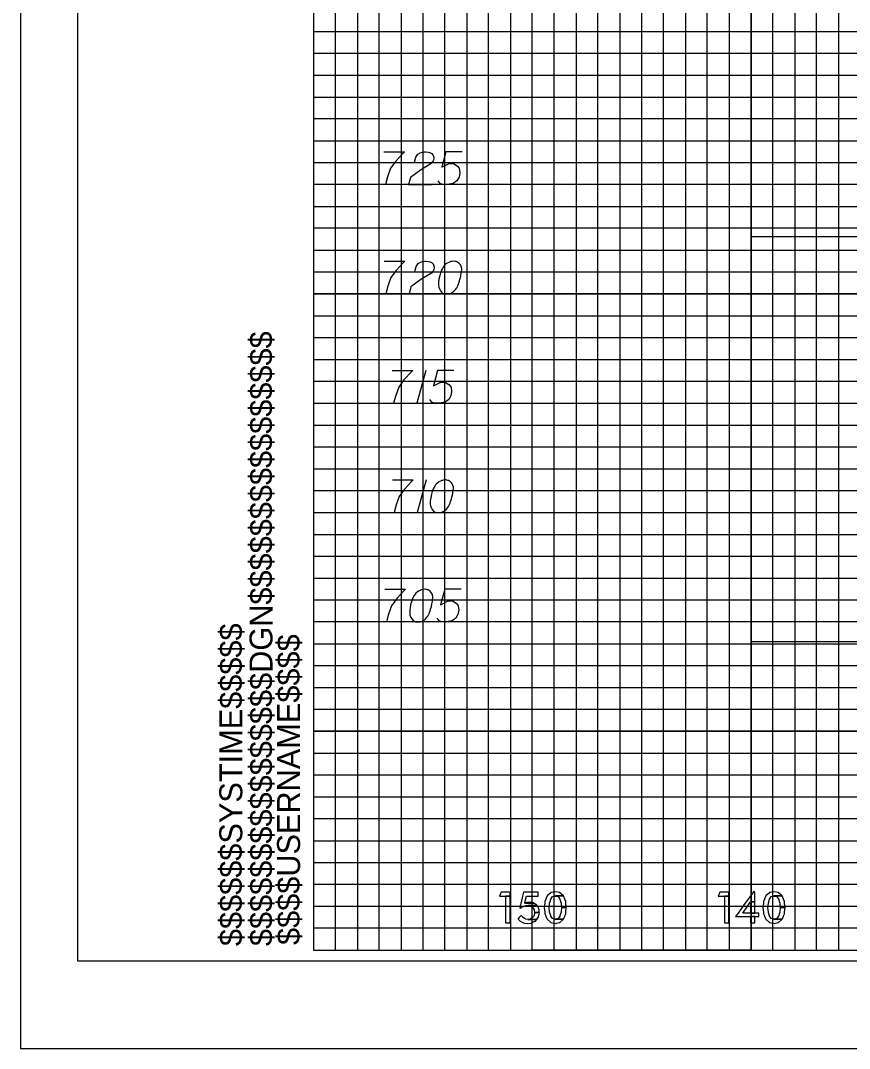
# Model space of a CAD drawing. Extents: x -13 to 323, y -5 to 1431.
# Drawn here: x -13.4 to 24.5, y 1095.5 to 1142.5 of the extents above; entities that cross this region are included whole.
import ezdxf

# ---------------------------------------------------------------- set-up
doc = ezdxf.new("R2010")
doc.units = 0
for name, color, linetype in [('Prop XS Elevation Labels', 7, 'Continuous'), ('Prop XS Offset Labels', 7, 'Continuous'), ('Scratch_Level_3', 7, 'Continuous'), ('Sheet Cross Section CELL', 7, 'Continuous'), ('Sheet Cross Section Grid Major CELL', 7, 'Continuous'), ('Sheet Cross Section Grid Middle CELL', 7, 'Continuous'), ('Sheet Cross Section Grid Minor 1 CELL', 7, 'Continuous'), ('Sheet Cross Section Grid Minor 2 CELL', 7, 'Continuous'), ('Sheet Cutting Line CELL', 7, 'Continuous'), ('Sheet DOT Grid CELL', 7, 'Continuous'), ('Sheet Plot Border Inside CELL', 7, 'Continuous'), ('Sheet Plot Border Outside CELL', 7, 'Continuous')]:
    doc.layers.add(name, color=color, linetype=linetype)

msp = doc.modelspace()

# ---------------------------------------------------------------- linework, layer by layer
at = {"layer": 'Prop XS Elevation Labels'}
for p, q in [((5.124, 1126.5), (4.723, 1125)), ((5.142, 1121.5), (4.74, 1120))]:
    msp.add_line(p, q, dxfattribs=at)
for points in [[(3.211, 1136.5), (4.155, 1136.5), (4.096, 1136.441), (3.754, 1136.075), (3.518, 1135.744), (3.376, 1135.354), (3.281, 1135)], [(4.616, 1136.028), (4.675, 1136.252), (4.77, 1136.394), (4.876, 1136.453), (4.982, 1136.488), (5.065, 1136.5), (5.124, 1136.5), (5.23, 1136.488), (5.301, 1136.465), (5.337, 1136.453), (5.408, 1136.417), (5.443, 1136.37), (5.467, 1136.323), (5.478, 1136.287), (5.49, 1136.24), (5.49, 1136.181), (5.478, 1136.122), (5.467, 1136.087), (5.443, 1136.039), (5.408, 1135.992), (5.372, 1135.957), (4.888, 1135.661), (4.427, 1135.319), (4.345, 1135), (5.419, 1135)], [(6.789, 1136.5), (6.045, 1136.5), (5.856, 1135.791), (6.199, 1135.969), (6.4, 1135.969), (6.565, 1135.862), (6.66, 1135.744), (6.683, 1135.543), (6.648, 1135.342), (6.553, 1135.177), (6.388, 1135.047), (6.104, 1135), (5.892, 1135), (5.785, 1135.047), (5.691, 1135.177)], [(3.228, 1131.5), (4.173, 1131.5), (4.114, 1131.441), (3.772, 1131.075), (3.535, 1130.744), (3.394, 1130.354), (3.299, 1130)], [(4.634, 1131.028), (4.693, 1131.252), (4.787, 1131.394), (4.894, 1131.453), (5, 1131.488), (5.083, 1131.5), (5.142, 1131.5), (5.248, 1131.488), (5.319, 1131.465), (5.354, 1131.453), (5.425, 1131.417), (5.461, 1131.37), (5.484, 1131.323), (5.496, 1131.287), (5.508, 1131.24), (5.508, 1131.181), (5.496, 1131.122), (5.484, 1131.087), (5.461, 1131.039), (5.425, 1130.992), (5.39, 1130.957), (4.906, 1130.661), (4.445, 1130.319), (4.362, 1130), (5.437, 1130)], [(6.417, 1131.5), (6.394, 1131.5), (6.323, 1131.488), (6.276, 1131.476), (6.24, 1131.465), (6.181, 1131.441), (6.11, 1131.406), (6.051, 1131.37), (5.992, 1131.323), (5.957, 1131.276), (5.921, 1131.217), (5.886, 1131.158), (5.85, 1131.087), (5.827, 1131.039), (5.803, 1130.969), (5.768, 1130.85), (5.732, 1130.673), (5.709, 1130.531), (5.709, 1130.402), (5.721, 1130.307), (5.768, 1130.201), (5.803, 1130.142), (5.862, 1130.071), (5.933, 1130.024), (5.968, 1130.012), (6.039, 1130), (6.098, 1130), (6.193, 1130.012), (6.276, 1130.035), (6.335, 1130.071), (6.417, 1130.13), (6.453, 1130.165), (6.5, 1130.213), (6.535, 1130.26), (6.559, 1130.295), (6.583, 1130.354), (6.594, 1130.378), (6.618, 1130.437), (6.642, 1130.508), (6.665, 1130.579), (6.677, 1130.626), (6.689, 1130.661), (6.701, 1130.709), (6.724, 1130.815), (6.736, 1130.874), (6.748, 1130.933), (6.76, 1131.016), (6.772, 1131.122), (6.772, 1131.158), (6.76, 1131.205), (6.748, 1131.252), (6.713, 1131.323), (6.677, 1131.37), (6.642, 1131.406), (6.594, 1131.441), (6.547, 1131.465), (6.512, 1131.476), (6.476, 1131.488), (6.417, 1131.5)], [(3.589, 1126.5), (4.533, 1126.5), (4.474, 1126.441), (4.132, 1126.075), (3.896, 1125.744), (3.754, 1125.354), (3.659, 1125)], [(6.411, 1126.5), (5.667, 1126.5), (5.478, 1125.791), (5.821, 1125.969), (6.022, 1125.969), (6.187, 1125.862), (6.282, 1125.744), (6.305, 1125.543), (6.27, 1125.342), (6.175, 1125.177), (6.01, 1125.047), (5.726, 1125), (5.514, 1125), (5.408, 1125.047), (5.313, 1125.177)], [(3.606, 1121.5), (4.551, 1121.5), (4.492, 1121.441), (4.149, 1121.075), (3.913, 1120.744), (3.772, 1120.354), (3.677, 1120)], [(6.039, 1121.5), (6.016, 1121.5), (5.945, 1121.488), (5.898, 1121.476), (5.862, 1121.465), (5.803, 1121.441), (5.732, 1121.406), (5.673, 1121.37), (5.614, 1121.323), (5.579, 1121.276), (5.543, 1121.217), (5.508, 1121.158), (5.472, 1121.087), (5.449, 1121.039), (5.425, 1120.969), (5.39, 1120.85), (5.354, 1120.673), (5.331, 1120.531), (5.331, 1120.402), (5.343, 1120.307), (5.39, 1120.201), (5.425, 1120.142), (5.484, 1120.071), (5.555, 1120.024), (5.591, 1120.012), (5.661, 1120), (5.72, 1120), (5.815, 1120.012), (5.898, 1120.035), (5.957, 1120.071), (6.039, 1120.13), (6.075, 1120.165), (6.122, 1120.213), (6.157, 1120.26), (6.181, 1120.295), (6.205, 1120.354), (6.217, 1120.378), (6.24, 1120.437), (6.264, 1120.508), (6.287, 1120.579), (6.299, 1120.626), (6.311, 1120.661), (6.323, 1120.709), (6.347, 1120.815), (6.358, 1120.874), (6.37, 1120.933), (6.382, 1121.016), (6.394, 1121.122), (6.394, 1121.158), (6.382, 1121.205), (6.37, 1121.252), (6.335, 1121.323), (6.299, 1121.37), (6.264, 1121.406), (6.217, 1121.441), (6.169, 1121.465), (6.134, 1121.476), (6.098, 1121.488), (6.039, 1121.5)], [(3.258, 1116.5), (4.203, 1116.5), (4.144, 1116.441), (3.801, 1116.075), (3.565, 1115.744), (3.423, 1115.354), (3.329, 1115)], [(5.1, 1116.5), (5.077, 1116.5), (5.006, 1116.488), (4.959, 1116.476), (4.923, 1116.465), (4.864, 1116.441), (4.793, 1116.406), (4.734, 1116.37), (4.675, 1116.323), (4.64, 1116.276), (4.604, 1116.217), (4.569, 1116.158), (4.534, 1116.087), (4.51, 1116.039), (4.486, 1115.969), (4.451, 1115.85), (4.415, 1115.673), (4.392, 1115.531), (4.392, 1115.402), (4.404, 1115.307), (4.451, 1115.201), (4.486, 1115.142), (4.545, 1115.071), (4.616, 1115.024), (4.652, 1115.012), (4.723, 1115), (4.781, 1115), (4.876, 1115.012), (4.959, 1115.035), (5.018, 1115.071), (5.1, 1115.13), (5.136, 1115.165), (5.183, 1115.213), (5.219, 1115.26), (5.242, 1115.295), (5.266, 1115.354), (5.278, 1115.378), (5.301, 1115.437), (5.325, 1115.508), (5.349, 1115.579), (5.36, 1115.626), (5.372, 1115.661), (5.384, 1115.709), (5.408, 1115.815), (5.419, 1115.874), (5.431, 1115.933), (5.443, 1116.016), (5.455, 1116.122), (5.455, 1116.158), (5.443, 1116.205), (5.431, 1116.252), (5.396, 1116.323), (5.36, 1116.37), (5.325, 1116.406), (5.278, 1116.441), (5.23, 1116.465), (5.195, 1116.476), (5.16, 1116.488), (5.1, 1116.5)], [(6.742, 1116.5), (5.998, 1116.5), (5.809, 1115.791), (6.152, 1115.969), (6.352, 1115.969), (6.518, 1115.862), (6.612, 1115.744), (6.636, 1115.543), (6.6, 1115.342), (6.506, 1115.177), (6.341, 1115.047), (6.057, 1115), (5.845, 1115), (5.738, 1115.047), (5.644, 1115.177)]]:
    msp.add_lwpolyline(points, dxfattribs=at)
at = {"layer": 'Prop XS Offset Labels'}
for points in [[(8.581, 1102.641), (8.492, 1102.459), (8.99, 1102.459), (8.99, 1102.641)], [(9.427, 1101.94), (9.424, 1101.928), (9.495, 1101.928), (9.508, 1101.94), (9.524, 1101.954), (9.595, 1101.997), (9.627, 1102.007), (9.697, 1102.029), (9.811, 1102.035), (10.219, 1102.035), (10.211, 1102.05), (10.076, 1102.145), (9.655, 1102.145), (9.658, 1102.158), (9.658, 1102.158), (9.663, 1102.178), (9.738, 1102.456), (10.263, 1102.456), (10.263, 1102.641), (9.6, 1102.641), (9.554, 1102.456), (9.486, 1102.178), (9.481, 1102.158), (9.478, 1102.145), (9.454, 1102.05), (9.451, 1102.035), (9.449, 1102.029), (9.444, 1102.007), (9.441, 1101.997), (9.431, 1101.954)], [(10.851, 1101.255), (11.051, 1101.214), (11.245, 1101.255), (11.256, 1101.257), (11.422, 1101.409), (11.047, 1101.409), (11.038, 1101.411), (11.033, 1101.413), (10.928, 1101.442), (10.841, 1101.555), (10.841, 1101.556), (10.841, 1101.556), (10.813, 1101.657), (10.813, 1101.659), (10.793, 1101.732), (10.792, 1101.736), (10.774, 1101.939), (10.774, 1101.941), (10.774, 1101.943), (10.792, 1102.145), (10.812, 1102.222), (10.813, 1102.224), (10.839, 1102.322), (10.84, 1102.325), (10.928, 1102.44), (11.041, 1102.469), (11.045, 1102.47), (11.055, 1102.473), (11.425, 1102.473), (11.262, 1102.622), (11.254, 1102.624), (11.053, 1102.668), (11.053, 1102.668), (10.845, 1102.624), (10.843, 1102.622), (10.681, 1102.473), (10.678, 1102.47), (10.678, 1102.469), (10.665, 1102.44), (10.618, 1102.325), (10.617, 1102.322), (10.577, 1102.224), (10.576, 1102.222), (10.568, 1102.145), (10.547, 1101.943), (10.547, 1101.941), (10.547, 1101.939), (10.567, 1101.736), (10.568, 1101.732), (10.575, 1101.659), (10.575, 1101.657), (10.616, 1101.556), (10.617, 1101.555), (10.663, 1101.442), (10.675, 1101.413), (10.676, 1101.411), (10.679, 1101.409), (10.848, 1101.257)], [(18.581, 1102.641), (18.492, 1102.459), (18.99, 1102.459), (18.99, 1102.641)], [(19.411, 1101.693), (19.297, 1101.534), (20.35, 1101.534), (20.35, 1101.693), (19.618, 1101.693), (19.878, 1102.059), (19.935, 1102.139), (19.977, 1102.199), (20.179, 1102.199), (20.179, 1102.668), (20.114, 1102.668), (19.775, 1102.199), (19.733, 1102.139), (19.675, 1102.059)], [(20.851, 1101.255), (21.051, 1101.214), (21.245, 1101.255), (21.256, 1101.257), (21.422, 1101.409), (21.047, 1101.409), (21.038, 1101.411), (21.033, 1101.413), (20.928, 1101.442), (20.841, 1101.555), (20.841, 1101.556), (20.841, 1101.556), (20.813, 1101.657), (20.813, 1101.659), (20.793, 1101.732), (20.792, 1101.736), (20.774, 1101.939), (20.774, 1101.941), (20.774, 1101.943), (20.792, 1102.145), (20.812, 1102.222), (20.813, 1102.224), (20.839, 1102.322), (20.84, 1102.325), (20.928, 1102.44), (21.041, 1102.469), (21.045, 1102.47), (21.055, 1102.473), (21.425, 1102.473), (21.262, 1102.622), (21.254, 1102.624), (21.053, 1102.668), (21.053, 1102.668), (20.845, 1102.624), (20.843, 1102.622), (20.681, 1102.473), (20.678, 1102.47), (20.678, 1102.469), (20.665, 1102.44), (20.618, 1102.325), (20.617, 1102.322), (20.577, 1102.224), (20.576, 1102.222), (20.568, 1102.145), (20.547, 1101.943), (20.547, 1101.941), (20.547, 1101.939), (20.567, 1101.736), (20.567, 1101.732), (20.575, 1101.659), (20.575, 1101.657), (20.616, 1101.556), (20.617, 1101.555), (20.663, 1101.442), (20.675, 1101.413), (20.676, 1101.411), (20.679, 1101.409), (20.848, 1101.257)], [(8.781, 1102.459), (8.781, 1101.25), (8.99, 1101.25), (8.99, 1102.459)], [(9.692, 1102.158), (9.655, 1102.145), (10.076, 1102.145), (10.058, 1102.158), (9.961, 1102.178), (9.75, 1102.178)], [(9.888, 1102.192), (9.75, 1102.178), (9.96, 1102.178), (9.888, 1102.192)], [(11.312, 1102.145), (11.328, 1101.943), (11.555, 1101.943), (11.536, 1102.145), (11.528, 1102.222), (11.527, 1102.224), (11.527, 1102.224), (11.488, 1102.322), (11.488, 1102.322), (11.487, 1102.325), (11.441, 1102.44), (11.44, 1102.44), (11.429, 1102.469), (11.428, 1102.47), (11.425, 1102.473), (11.055, 1102.473), (11.065, 1102.47), (11.068, 1102.469), (11.175, 1102.44), (11.262, 1102.325), (11.265, 1102.322), (11.291, 1102.224), (11.291, 1102.222)], [(18.781, 1102.459), (18.781, 1101.25), (18.99, 1101.25), (18.99, 1102.459)], [(19.97, 1102.059), (19.97, 1101.693), (20.179, 1101.693), (20.179, 1102.059), (20.179, 1102.139), (20.179, 1102.199), (19.977, 1102.199), (19.973, 1102.139)], [(21.312, 1102.145), (21.328, 1101.943), (21.555, 1101.943), (21.536, 1102.145), (21.528, 1102.222), (21.527, 1102.224), (21.527, 1102.224), (21.488, 1102.322), (21.488, 1102.322), (21.487, 1102.325), (21.441, 1102.44), (21.44, 1102.44), (21.429, 1102.469), (21.428, 1102.47), (21.425, 1102.473), (21.055, 1102.473), (21.065, 1102.47), (21.068, 1102.469), (21.175, 1102.44), (21.262, 1102.325), (21.265, 1102.322), (21.291, 1102.224), (21.291, 1102.222)], [(9.424, 1101.928), (9.482, 1101.916), (9.495, 1101.928)], [(9.9, 1101.418), (9.793, 1101.399), (10.204, 1101.399), (10.22, 1101.418), (10.221, 1101.419), (10.222, 1101.42), (10.222, 1101.42), (10.259, 1101.466), (10.268, 1101.477), (10.27, 1101.483), (10.284, 1101.535), (10.299, 1101.59), (10.322, 1101.674), (10.318, 1101.721), (10.105, 1101.721), (10.097, 1101.674), (10.082, 1101.59), (10.047, 1101.535), (10.014, 1101.483), (10.004, 1101.477), (9.987, 1101.466), (9.913, 1101.42), (9.905, 1101.419)], [(10.083, 1101.841), (10.105, 1101.721), (10.318, 1101.721), (10.307, 1101.841), (10.307, 1101.841), (10.303, 1101.881), (10.284, 1101.916), (10.278, 1101.928), (10.271, 1101.94), (10.263, 1101.954), (10.24, 1101.997), (10.235, 1102.007), (10.223, 1102.029), (10.219, 1102.035), (9.811, 1102.035), (9.838, 1102.029), (9.928, 1102.007), (9.943, 1101.997), (10.003, 1101.954), (10.024, 1101.94), (10.031, 1101.928), (10.038, 1101.916), (10.059, 1101.881)], [(11.058, 1101.411), (11.047, 1101.409), (11.422, 1101.409), (11.425, 1101.411), (11.426, 1101.413), (11.438, 1101.442), (11.485, 1101.555), (11.485, 1101.556), (11.527, 1101.657), (11.528, 1101.659), (11.535, 1101.732), (11.535, 1101.736), (11.555, 1101.939), (11.556, 1101.941), (11.555, 1101.943), (11.328, 1101.943), (11.328, 1101.941), (11.328, 1101.939), (11.312, 1101.736), (11.312, 1101.732), (11.292, 1101.659), (11.291, 1101.657), (11.264, 1101.556), (11.263, 1101.555), (11.175, 1101.442), (11.063, 1101.413)], [(21.058, 1101.411), (21.047, 1101.409), (21.422, 1101.409), (21.425, 1101.411), (21.426, 1101.413), (21.438, 1101.442), (21.485, 1101.555), (21.485, 1101.556), (21.527, 1101.657), (21.528, 1101.659), (21.535, 1101.732), (21.535, 1101.736), (21.555, 1101.939), (21.556, 1101.941), (21.555, 1101.943), (21.328, 1101.943), (21.328, 1101.941), (21.328, 1101.939), (21.312, 1101.736), (21.312, 1101.732), (21.292, 1101.659), (21.291, 1101.657), (21.264, 1101.556), (21.263, 1101.555), (21.175, 1101.442), (21.063, 1101.413)], [(9.626, 1101.233), (9.762, 1101.214), (9.959, 1101.233), (9.968, 1101.237), (10.091, 1101.297), (10.091, 1101.297), (10.141, 1101.321), (10.185, 1101.375), (10.204, 1101.399), (9.793, 1101.399), (9.683, 1101.418), (9.682, 1101.419), (9.679, 1101.42), (9.596, 1101.466), (9.586, 1101.477), (9.58, 1101.483), (9.58, 1101.483), (9.529, 1101.535), (9.497, 1101.585), (9.497, 1101.585), (9.451, 1101.535), (9.404, 1101.483), (9.399, 1101.477), (9.39, 1101.466), (9.348, 1101.42), (9.347, 1101.419), (9.348, 1101.418), (9.363, 1101.399), (9.382, 1101.375), (9.445, 1101.321), (9.474, 1101.297), (9.598, 1101.237)], [(19.97, 1101.534), (19.97, 1101.25), (20.179, 1101.25), (20.179, 1101.534)]]:
    msp.add_lwpolyline(points, close=True, dxfattribs=at)
at = {"layer": 'Scratch_Level_3'}
msp.add_lwpolyline([(20, 1132.62), (300, 1132.62), (300, 1114.089), (20, 1114.089)], close=True, dxfattribs=at)
at = {"layer": 'Sheet Cross Section CELL'}
msp.add_line((0, 1100), (0, 1100), dxfattribs=at)
msp.add_line((0, 1100), (0, 1100), dxfattribs=at)
msp.add_line((0, 1100), (0, 1100), dxfattribs=at)
msp.add_line((0, 1100), (0, 1100), dxfattribs=at)
msp.add_line((0, 1100), (0, 1100), dxfattribs=at)
msp.add_line((0, 1100), (0, 1100), dxfattribs=at)
msp.add_line((0, 1100), (0, 1100), dxfattribs=at)
msp.add_lwpolyline([(320, 1310), (0, 1310), (0, 1100), (320, 1100)], close=True, dxfattribs=at)
at = {"layer": 'Sheet Cross Section Grid Major CELL'}
for p, q in [((10, 1100), (10, 1310)), ((20, 1310), (20, 1100)), ((20, 1100), (10, 1100))]:
    msp.add_line(p, q, dxfattribs=at)
for points in [[(0, 1140), (320, 1140), (320, 1130), (0, 1130)], [(0, 1120), (320, 1120), (320, 1110), (0, 1110)]]:
    msp.add_lwpolyline(points, dxfattribs=at)
at = {"layer": 'Sheet Cross Section Grid Middle CELL'}
for points in [[(5, 1310), (5, 1100), (15, 1100), (15, 1310)], [(0, 1125), (320, 1125), (320, 1135), (0, 1135)], [(0, 1105), (320, 1105), (320, 1115), (0, 1115)]]:
    msp.add_lwpolyline(points, dxfattribs=at)
at = {"layer": 'Sheet Cross Section Grid Minor 1 CELL'}
for points in [[(0, 1142), (320, 1142), (320, 1141), (0, 1141)], [(0, 1139), (320, 1139), (320, 1138), (0, 1138)], [(0, 1137), (320, 1137), (320, 1136), (0, 1136)], [(0, 1134), (320, 1134), (320, 1133), (0, 1133)], [(0, 1132), (320, 1132), (320, 1131), (0, 1131)], [(0, 1129), (320, 1129), (320, 1128), (0, 1128)], [(0, 1127), (320, 1127), (320, 1126), (0, 1126)], [(0, 1124), (320, 1124), (320, 1123), (0, 1123)], [(0, 1122), (320, 1122), (320, 1121), (0, 1121)], [(0, 1119), (320, 1119), (320, 1118), (0, 1118)], [(0, 1117), (320, 1117), (320, 1116), (0, 1116)], [(0, 1114), (320, 1114), (320, 1113), (0, 1113)], [(0, 1112), (320, 1112), (320, 1111), (0, 1111)], [(0, 1109), (320, 1109), (320, 1108), (0, 1108)], [(0, 1107), (320, 1107), (320, 1106), (0, 1106)], [(0, 1104), (320, 1104), (320, 1103), (0, 1103)], [(0, 1102), (320, 1102), (320, 1101), (0, 1101)]]:
    msp.add_lwpolyline(points, dxfattribs=at)
at = {"layer": 'Sheet Cross Section Grid Minor 2 CELL'}
for points in [[(0, 1100), (1, 1100), (1, 1310), (2, 1310), (2, 1100)], [(2, 1100), (3, 1100), (3, 1310), (4, 1310), (4, 1100)], [(5, 1100), (6, 1100), (6, 1310), (7, 1310), (7, 1100)], [(7, 1100), (8, 1100), (8, 1310), (9, 1310), (9, 1100)], [(10, 1100), (11, 1100), (11, 1310), (12, 1310), (12, 1100)], [(12, 1100), (13, 1100), (13, 1310), (14, 1310), (14, 1100)], [(15, 1100), (16, 1100), (16, 1310), (17, 1310), (17, 1100)], [(17, 1100), (18, 1100), (18, 1310), (19, 1310), (19, 1100)], [(20, 1100), (21, 1100), (21, 1310), (22, 1310), (22, 1100)], [(22, 1100), (23, 1100), (23, 1310), (24, 1310), (24, 1100)]]:
    msp.add_lwpolyline(points, dxfattribs=at)
at = {"layer": 'Sheet Cutting Line CELL'}
for p, q in [((-13.4, 1314.5), (-13.4, 1095.5)), ((-13.4, 1095.5), (323.3, 1095.5))]:
    msp.add_line(p, q, dxfattribs=at)
at = {"layer": 'Sheet DOT Grid CELL'}
for p, q in [((10, 1100), (10, 1310)), ((20, 1100), (20, 1310)), ((0, 1140), (320, 1140)), ((0, 1130), (320, 1130)), ((0, 1120), (320, 1120)), ((0, 1110), (320, 1110))]:
    msp.add_line(p, q, dxfattribs=at)
at = {"layer": 'Sheet Plot Border Inside CELL'}
msp.add_lwpolyline([(-10.8, 1099.5), (322.4, 1099.5), (322.4, 1310.5), (-10.8, 1310.5)], close=True, dxfattribs=at)
at = {"layer": 'Sheet Plot Border Outside CELL'}
msp.add_lwpolyline([(-13.4, 1095.5), (323.3, 1095.5), (323.3, 1314.5), (-13.4, 1314.5)], close=True, dxfattribs=at)

# ---------------------------------------------------------------- texts
at = {"layer": 'Sheet Cross Section CELL'}
for s, p in [('$$$$$$$$$$$$$$$$DGN$$$$$$$$$$$$$$$$', (-1.88, 1100.18)), ('$$$$$$SYSTIME$$$$$', (-3.26, 1100.18)), ('$$$$USERNAME$$$$', (-0.62, 1100.23))]:
    msp.add_text(s, height=1.05, rotation=90, dxfattribs=at).set_placement(p)

doc.saveas('drawing.dxf')
